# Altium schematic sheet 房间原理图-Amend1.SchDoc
size A4
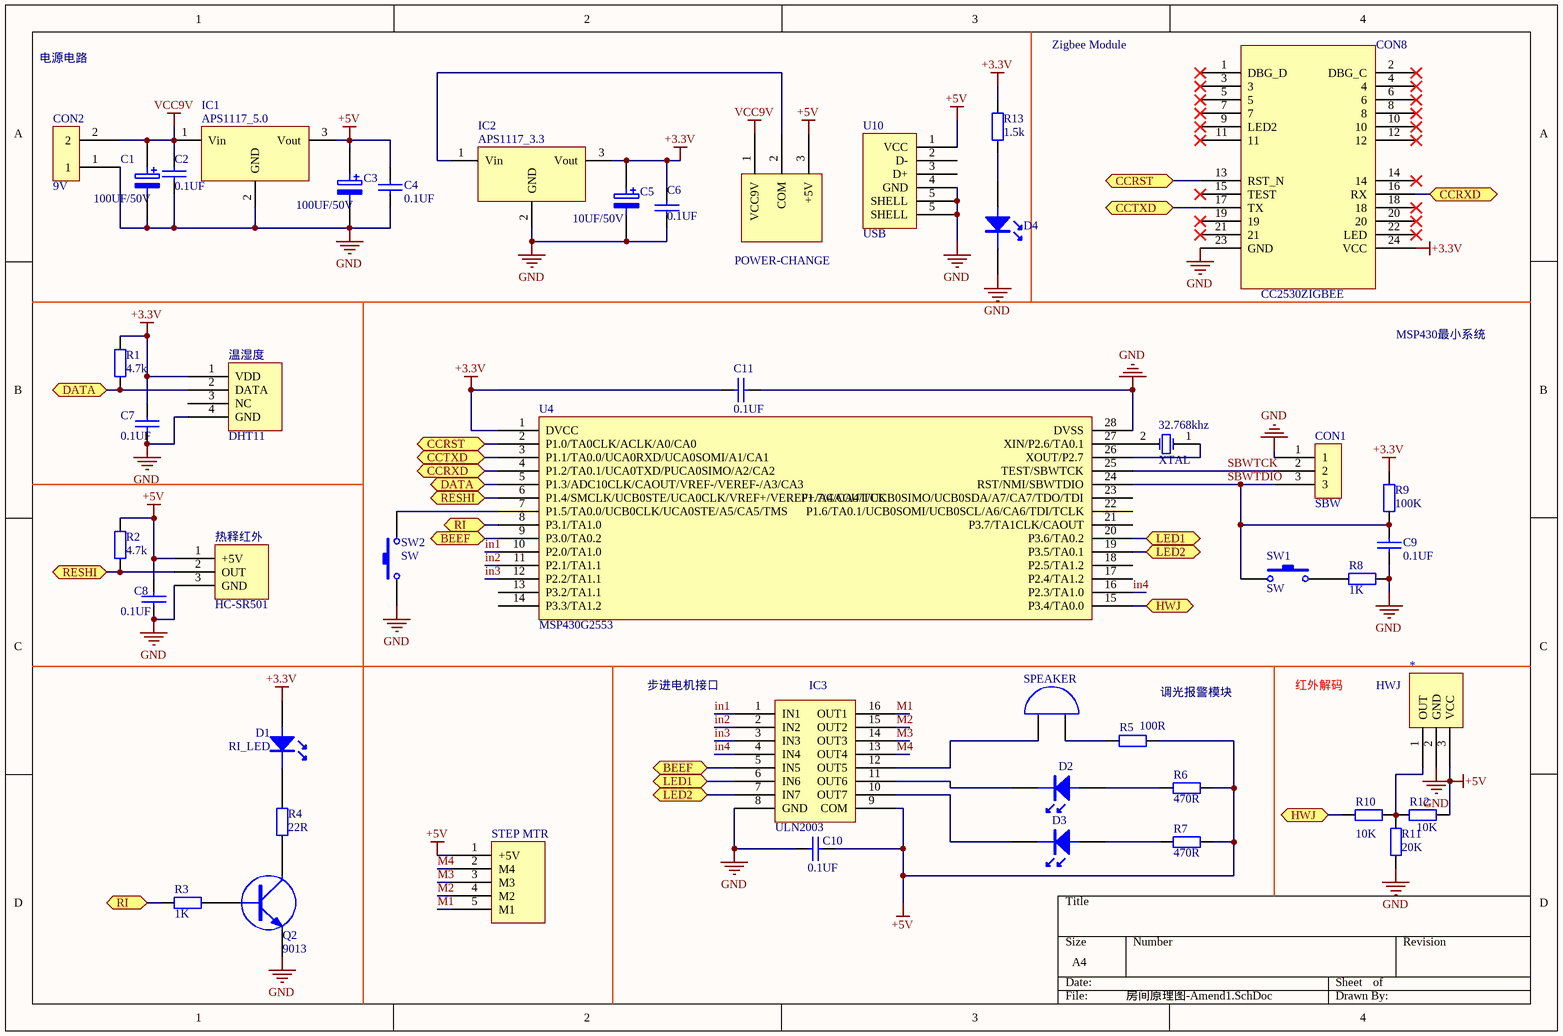
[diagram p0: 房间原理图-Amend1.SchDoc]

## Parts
(Parts that share a designator on the sheet are numbered #1, #2 ... from top to bottom, then left to right.)
32.768khz  XTAL  [BCY-W2/D3.1]
*#1  POWER-CHANGE
*#2  HWJ
?  STEP MTR
C1  100UF/50V
C2  0.1UF
C3  100UF/50V
C4  0.1UF
C5  10UF/50V
C6  0.1UF
C7  0.1UF
C8  0.1UF
C9  0.1UF
C10  0.1UF
C11  0.1UF
CON1  SBW  [2.54*1*3]
CON2  9V  [2.54*2*1]
CON8  CC2530ZIGBEE
D1  RI_LED
D2  LED  (value not drawn)
D3  LED  (value not drawn)
D4  LED  (value not drawn)
IC1  APS1117_5.0  [TO220H]
IC2  APS1117_3.3  [TO220H]
IC3  ULN2003
Q2  9013
R1  4.7k  [C0805]
R2  4.7k  [C0805]
R3  1K  [C0805]
R4  22R  [C0805]
R5  100R  [C0805]
R6  470R  [C0805]
R7  470R  [C0805]
R8  1K  [C0805]
R9  100K  [C0805]
R10  10K  [C0805]
R11  20K  [C0805]
R12  10K  [C0805]
R13  1.5k  [C0805]
SPEAKER  (no value)
SW1  SW
SW2  SW
U4  MSP430G2553  [MSP430G2553]
U10  USB  [USB-B]
温湿度  DHT11
热释红外  HC-SR501

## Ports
BEEF, CCRST, CCRXD, CCTXD, DATA, HWJ, LED1, LED2, RESHI, RI

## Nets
+3.3V: C5.1 C6.1 C7.1 C11.1 CON8.24(VCC) D1.A IC2.3(Vout) R1.1 R9.1 R13.1 U4.1(DVCC) 温湿度.1(VDD)
+5V: *#1.3(+5V) *#2.3(VCC) ?.1(+5V) C3.1 C4.1 C8.1 C10.2 IC1.3(Vout) IC3.9(COM) R2.1 R5.1 R6.1 R7.1 R12.1 U10.1(VCC) 热释红外.1(+5V)
GND: *#2.2(GND) C1.2 C2.2 C3.2 C4.2 C5.2 C6.2 C7.2 C8.2 C9.2 C10.1 C11.2 CON1.1 CON2.1 CON8.23(GND) D4.K IC1.2(GND) IC2.2(GND) IC3.8(GND) Q2.3(E) R8.2 R11.2 SW2.2 U4.28(DVSS) U10.4(GND) U10.5(SHELL) 温湿度.4(GND) 热释红外.3(GND)
VCC9V: *#1.1(VCC9V) C1.1 C2.1 CON2.2 IC1.1(Vin)
BEEF: IC3.5(IN5) U4.9(P3.0/TA0.2) ; port BEEF
CCRST: CON8.13(RST_N) U4.2(P1.0/TA0CLK/ACLK/A0/CA0) ; port CCRST
CCRXD: CON8.16(RX) U4.4(P1.2/TA0.1/UCA0TXD/PUCA0SIMO/A2/CA2) ; port CCRXD
CCTXD: CON8.17(TX) U4.3(P1.1/TA0.0/UCA0RXD/UCA0SOMI/A1/CA1) ; port CCTXD
DATA: R1.2 U4.5(P1.3/ADC10CLK/CAOUT/VREF-/VEREF-/A3/CA3) 温湿度.2(DATA) ; port DATA
HWJ: R10.2 U4.15(P3.4/TA0.0) ; port HWJ
in1: IC3.1(IN1) U4.10(P2.0/TA1.0)
in2: IC3.2(IN2) U4.11(P2.1/TA1.1)
in3: IC3.3(IN3) U4.12(P2.2/TA1.1)
in4: IC3.4(IN4) U4.16(P2.3/TA1.0)
LED1: IC3.6(IN6) U4.20(P3.6/TA0.2) ; port LED1
LED2: IC3.7(IN7) U4.19(P3.5/TA0.1) ; port LED2
M1: ?.5(M1) IC3.16(OUT1)
M2: ?.4(M2) IC3.15(OUT2)
M3: ?.3(M3) IC3.14(OUT3)
M4: ?.2(M4) IC3.13(OUT4)
RESHI: R2.2 U4.6(P1.4/SMCLK/UCB0STE/UCA0CLK/VREF+/VEREF+/A4/CA4/TCK) 热释红外.2(OUT) ; port RESHI
RI: R3.2 U4.8(P3.1/TA1.0) ; port RI
SBWTCK: CON1.2 U4.25(TEST/SBWTCK)
SBWTDIO: C9.1 CON1.3 R9.2 SW1.2 U4.24(RST/NMI/SBWTDIO)
Net32.768khz_1: 32.768khz.1(OSC1) U4.26(XOUT/P2.7)
Net32.768khz_2: 32.768khz.2(OSC2) U4.27(XIN/P2.6/TA0.1)
Net*#1_2: *#1.2(COM) IC2.1(Vin)
Net*#2_1: *#2.1(OUT) R10.1 R11.1 R12.2
NetD1_K: D1.K R4.1
NetD2_A: D2.A R6.2
NetD2_K: D2.K IC3.11(OUT6)
NetD3_A: D3.A R7.2
NetD3_K: D3.K IC3.10(OUT7)
NetD4_A: D4.A R13.2
NetIC3_12: IC3.12(OUT5) SPEAKER.1(A)
NetQ2_1: Q2.1(B) R3.1
NetQ2_2: Q2.2(C) R4.2
NetR5_2: R5.2 SPEAKER.2(B)
NetR8_1: R8.1 SW1.1
NetSW2_1: SW2.1 U4.7(P1.5/TA0.0/UCB0CLK/UCA0STE/A5/CA5/TMS)

Not connected (* = marked no-connect by the designer): CON8 1(DBG_D)* 2(DBG_C)* 3* 4* 5* 6* 7* 8* 9(LED2)* 10* 11* 12* 14* 15(TEST)* 18* 19* 20* 21* 22(LED)*; U4 13(P3.2/TA1.1) 14(P3.3/TA1.2) 17(P2.4/TA1.2) 18(P2.5/TA1.2) 21(P3.7/TA1CLK/CAOUT) 22(P1.6/TA0.1/UCB0SOMI/UCB0SCL/A6/CA6/TDI/TCLK) 23(P1.7/CAOUT/UCB0SIMO/UCB0SDA/A7/CA7/TDO/TDI); U10 2(D-) 3(D+); 温湿度 3(NC)

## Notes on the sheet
- 电源电路
- Zigbee Module
- MSP430最小系统
- 步进电机接口
- (near R5) 调光报警模块
- 红外解码

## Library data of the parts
32.768khz = XTAL: Crystal Oscillator
*#2 = Component_1
C1 C3 C5 = ELECTRO2: Electrolytic Capacitor
C2 C4 C6-C11 = CAP: Capacitor
CON1 = 2.54*1*3
CON2 = 2.54*2*1
D1 = LED
IC1 IC2 = VOLTREG
Q2 = NPN: NPN Transistor
R1-R13 = R0805
SPEAKER = BELL
U10 = USB-B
